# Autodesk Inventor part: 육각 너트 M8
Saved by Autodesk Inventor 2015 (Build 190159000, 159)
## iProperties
Created: 2024-12
Part Number: 육각 너트 M8
Material: 일반
Document SubType Name: Modeling
Designer: 102-5
Density: 1 g/cm^3
Appearance: 기본값
Author: 102-5
Author: jhkim
Description: 6각 너트 및 6각 가는 너트
Creation Date: 2024-11-28
Sending System: Autodesk Inventor 2025
Preprocessor: ST-DEVELOPER v20
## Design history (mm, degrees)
node "육각 너트 M81"
body "Solid1"
node "기준1"
